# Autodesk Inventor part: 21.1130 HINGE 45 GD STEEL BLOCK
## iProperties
Created: 2007-01
Part Number: 21.1130 HINGE 45 GD STEEL BLOCK
Material: Steel
Document SubType Name: Modeling
Designer: Andy Moles
Density: 7.85 g/cm^3
Author: Andy Moles
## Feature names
1. Base1
2. Extrusion1
3. Chamfer1
4. Extrusion2
5. Chamfer2
